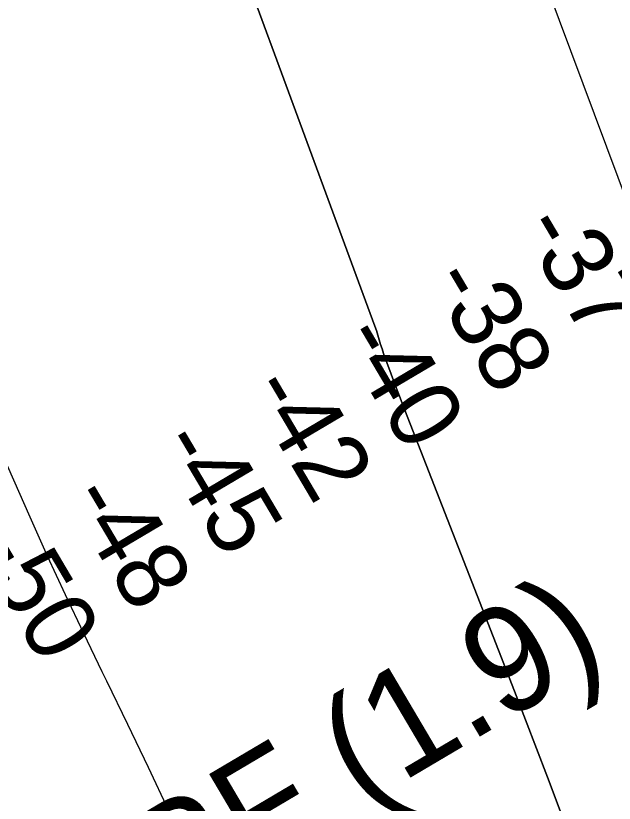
# Model space of a CAD drawing. Extents: x 3914892 to 3953151, y 242587 to 268572.
# Drawn here: x 3942012 to 3942580, y 252639 to 253385 of the extents above; entities that cross this region are included whole.
import ezdxf

# ---------------------------------------------------------------- set-up
doc = ezdxf.new("R2010")
doc.units = 0
for name, color, linetype in [('V-CHAN-NAID', 7, 'Continuous'), ('V-RIVR-RANG', 7, 'Continuous'), ('V-TOPO-DPTH', 7, 'Continuous'), ('V-TOPO-MAJR', 7, 'Continuous'), ('V-TOPO-MINR', 7, 'Continuous')]:
    doc.layers.add(name, color=color, linetype=linetype)

msp = doc.modelspace()

# ---------------------------------------------------------------- linework, layer by layer
at = {"layer": 'V-TOPO-DPTH'}
for points in [[(3942765.88, 252620.36), (3942745.78, 252680.5), (3942727.27, 252741.21), (3942704.38, 252821.97), (3942698.69, 252842.77), (3942693.25, 252863.62), (3942688.17, 252884.57), (3942683.35, 252905.58), (3942678.48, 252926.58), (3942673.31, 252947.5), (3942667.68, 252968.3), (3942661.74, 252989.02), (3942627.37, 253104.14), (3942618.6, 253132.38), (3942609.44, 253160.49), (3942599.67, 253188.39), (3942589.51, 253216.16), (3942583.4, 253232.3), (3942292.57, 254010.13)], [(3942765.88, 252620.36), (3942745.78, 252680.5), (3942727.27, 252741.21), (3942704.38, 252821.97), (3942698.69, 252842.77), (3942693.25, 252863.62), (3942688.17, 252884.57), (3942683.35, 252905.58), (3942678.48, 252926.58), (3942673.31, 252947.5), (3942667.68, 252968.3), (3942661.74, 252989.02), (3942627.37, 253104.14), (3942618.6, 253132.38), (3942609.44, 253160.49), (3942599.67, 253188.39), (3942589.51, 253216.16), (3942583.4, 253232.3), (3942292.57, 254010.13)], [(3942152.79, 253634.19), (3942352.74, 253091.35), (3942354.13, 253087.02), (3942355.51, 253082.68), (3942356.86, 253078.34), (3942358.2, 253073.99), (3942359.56, 253069.65), (3942360.98, 253065.33), (3942362.47, 253061.04), (3942364.02, 253056.76), (3942372.23, 253034.69), (3942374.38, 253028.95), (3942376.55, 253023.22), (3942378.75, 253017.49), (3942380.96, 253011.78), (3942485.14, 252745.32), (3942516.38, 252663.93), (3942546.95, 252582.3)], [(3942546.95, 252582.3), (3942516.38, 252663.93), (3942485.14, 252745.32), (3942380.96, 253011.78), (3942378.75, 253017.49), (3942376.55, 253023.22), (3942374.38, 253028.95), (3942372.23, 253034.69), (3942364.02, 253056.76), (3942362.47, 253061.04), (3942360.98, 253065.33), (3942359.56, 253069.65), (3942358.2, 253073.99), (3942356.86, 253078.34), (3942355.51, 253082.68), (3942354.13, 253087.02), (3942352.74, 253091.35), (3942152.79, 253634.19)]]:
    msp.add_lwpolyline(points, dxfattribs=at)
at = {"layer": 'V-TOPO-MAJR'}
msp.add_lwpolyline([(3942157.41, 252631.87), (3942138, 252672.94), (3942118.35, 252713.89), (3942098.54, 252754.77), (3942094.18, 252763.7), (3942076.64, 252800.15), (3942059.36, 252836.72), (3942042.48, 252873.47), (3942025.88, 252910.35), (3941932.55, 253120.63)], dxfattribs=at)
at = {"layer": 'V-TOPO-MINR'}
for points in [[(3942765.88, 252620.36), (3942745.78, 252680.5), (3942727.27, 252741.21), (3942704.38, 252821.97), (3942698.69, 252842.77), (3942693.25, 252863.62), (3942688.17, 252884.57), (3942683.35, 252905.58), (3942678.48, 252926.58), (3942673.31, 252947.5), (3942667.68, 252968.3), (3942661.74, 252989.02), (3942627.37, 253104.14), (3942618.6, 253132.38), (3942609.44, 253160.49), (3942599.67, 253188.39), (3942589.51, 253216.16), (3942583.4, 253232.3), (3942292.57, 254010.13)], [(3942546.95, 252582.3), (3942516.38, 252663.93), (3942485.14, 252745.32), (3942380.96, 253011.78), (3942378.75, 253017.49), (3942376.55, 253023.22), (3942374.38, 253028.95), (3942372.23, 253034.69), (3942364.02, 253056.76), (3942362.47, 253061.04), (3942360.98, 253065.33), (3942359.56, 253069.65), (3942358.2, 253073.99), (3942356.86, 253078.34), (3942355.51, 253082.68), (3942354.13, 253087.02), (3942352.74, 253091.35), (3942152.79, 253634.19)]]:
    msp.add_lwpolyline(points, dxfattribs=at)

# ---------------------------------------------------------------- texts
at = {"layer": 'V-CHAN-NAID'}
msp.add_text('RIVER PILOTS WHARF (1.9)', height=100, rotation=30.57923, dxfattribs=at).set_placement((3941060.03, 251879.63))
at = {"layer": 'V-RIVR-RANG'}
for s, p in [('-37', (3942488.77, 253184.57)), ('-38', (3942402.43, 253134.11)), ('-40', (3942317.97, 253080.49)), ('-42', (3942230.82, 253031.41)), ('-45', (3942145.14, 252979.83)), ('-48', (3942059.47, 252928.25)), ('-50', (3941972.05, 252879.62))]:
    msp.add_text(s, height=67, rotation=300.58694, dxfattribs=at).set_placement(p)

doc.saveas('drawing.dxf')
